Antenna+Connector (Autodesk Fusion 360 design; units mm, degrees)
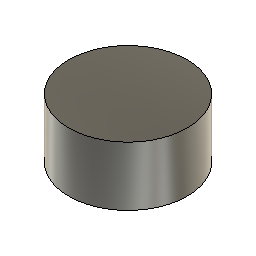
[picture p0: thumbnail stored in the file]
sketch "Sketch1" plane through (0, 0, 0) normal (0, 0, 1) x axis (1, 0, 0)
  circle C1 centre (0, 0) radius 1.5
  point P1 (0, 0)
  point P2 (0, 0)
  coincident P1 P2
  dimension "d2" diameter C1 = 3 (= "( 3 * Ratio ) * 1 mm")
extrude "Extrude1" new body sketch "Sketch1" along normal blind 1.5 (= "( 1.5 * Ratio ) * 1 mm")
